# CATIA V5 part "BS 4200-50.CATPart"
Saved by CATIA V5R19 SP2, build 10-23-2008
Part number: BS 4200-50
Bounding box of the stored display mesh (mm): x -47.487 to 47.487, y -47.487 to 47.487, z 0 to 165
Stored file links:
  C:\Users\Bora\Desktop\3D Katı model\BS serisi\BS 4200\BS 4200-50.CATPart
  C:\Program Files\Dassault Systemes\B19\intel_a\reffiles\standard\MetricThickPitch.txt
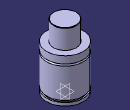
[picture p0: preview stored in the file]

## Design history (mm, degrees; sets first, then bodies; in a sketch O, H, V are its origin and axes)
Body1 (main body)
  Sketch1 on yz-plane, origin (0, 0, 0), H (0, 1, 0), V (0, 0, 1)
    point P2 (47.5, 90.5)
    point P5 (30, 164)
    point P7 (30, 164)
    point P11 (47.5, 95.5)
    point P13 (47.5, 95.5)
    point P14 (47.5, 90.5)
    line L1 (47.5, 13) -> (47.5, 90.5)
    line L2 (44.5, 13) -> (44.5, 8)
    line L3 (30, 164) -> (30, 114)
    arc A1 centre (29, 164) radius 1 from (30, 164) to (29, 165) ccw
    line L4 (47.5, 0) -> (47.5, 8)
    line L5 (47.5, 95.5) -> (47.5, 114)
    arc A2 centre (47.5, 93) radius 2.5 from (47.5, 95.5) to (47.5, 90.5) ccw
    line L6 (29, 165) -> (0, 165)
    point P15 (0, 165)
    line L7 (30, 114) -> (47.5, 114)
    line L8 (0, 0) -> (47.5, 0)
    line L9 (44.5, 13) -> (47.5, 13)
    line L10 (44.5, 8) -> (47.5, 8)
    coincidence: P15 V, P2 P14, P5 P7, P11 P13
    tangency: L6 A1
    horizontal: L7 H, L8 H, L9 H, L10 H
  Shaft1: profile Sketch1, axis Sketch1.V, angle 360
  Sketch2 on face of Shaft1 from Sketch1.L8, origin (0, 0, 0), H (1, 0, 0), V (0, -1, 0)
    point P1 (30, 0)
    distance P1 V = 30
  Hole1: placed by Sketch2, at (30, 0, 0) direction (0, 0, 1), diameter 6.647, depth 7, threaded "M8", thread diameter 8, thread depth 7, pitch 1.25
  CircPattern1: of Hole1, instances 4, angular step 90, axis from xy-plane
